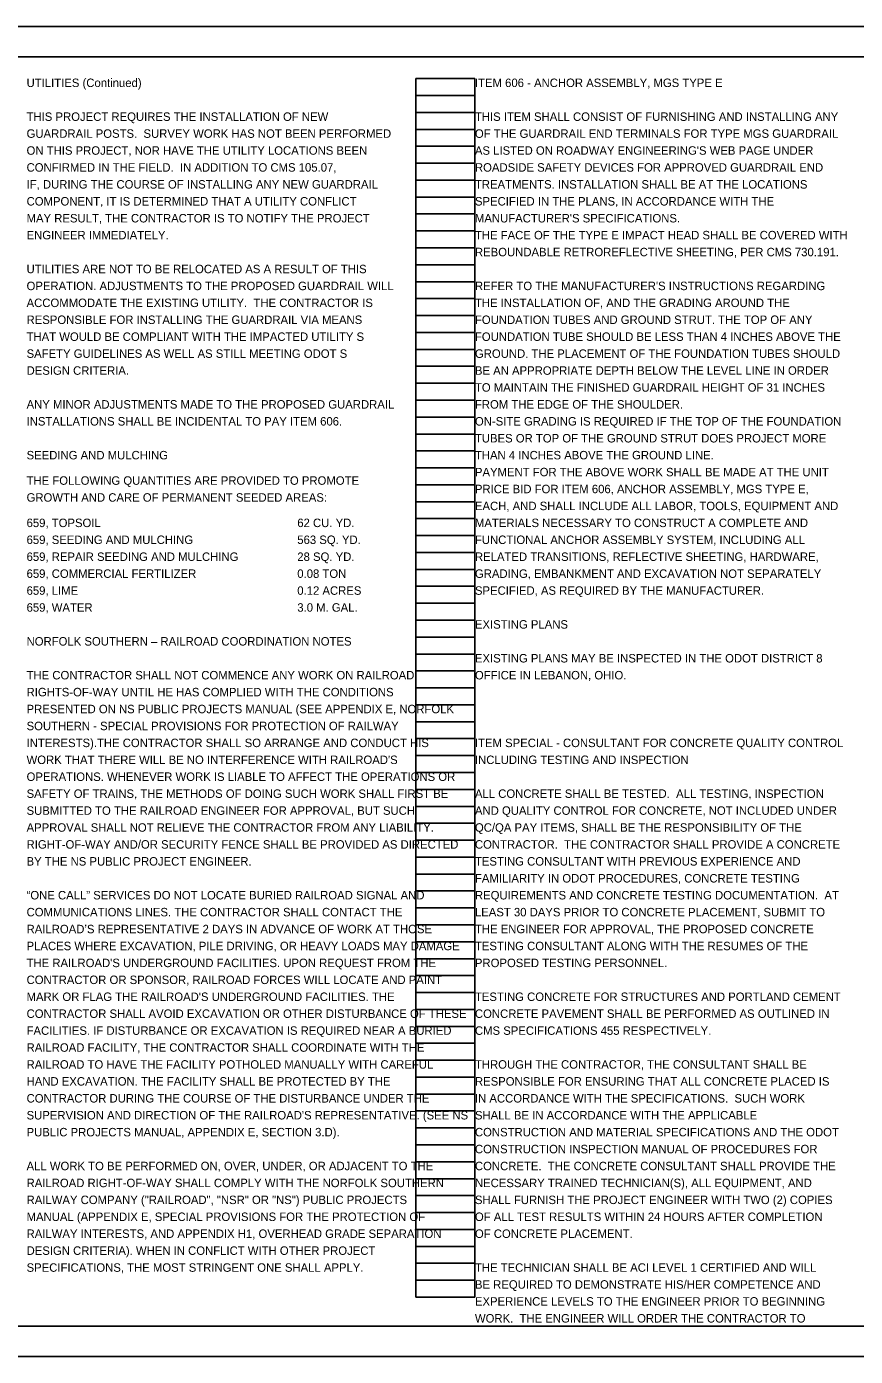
# Model space of a CAD drawing. Extents: x -15.3 to 74.8, y -11.5 to 47.6.
# Drawn here: x 9.82 to 23.54, y 0 to 22 of the extents above; entities that cross this region are included whole.
import ezdxf

# ---------------------------------------------------------------- set-up
doc = ezdxf.new("R2010")
doc.units = 0
for name, color, linetype in [('Default', 7, 'Continuous'), ('SH_Border', 7, 'Continuous'), ('SH_Cut_Line', 7, 'Continuous'), ('SH_Data', 7, 'Continuous'), ('SH_Text', 7, 'Continuous')]:
    doc.layers.add(name, color=color, linetype=linetype)

msp = doc.modelspace()

# ---------------------------------------------------------------- linework, layer by layer
at = {"layer": 'SH_Border'}
msp.add_lwpolyline([(1.5, 21.5), (33.5, 21.5), (33.5, 0.5), (1.5, 0.5)], close=True, dxfattribs=at)
at = {"layer": 'SH_Cut_Line'}
msp.add_lwpolyline([(0, 0), (34, 0), (34, 22), (0, 22)], close=True, dxfattribs=at)
at = {"layer": 'SH_Data'}
for p, q in [((16.26, 0.98), (16.26, 21.14)), ((16.26, 21.14), (17.24, 21.14)), ((17.24, 0.98), (17.24, 21.14)), ((16.26, 20.86), (17.24, 20.86)), ((16.26, 20.58), (17.24, 20.58)), ((16.26, 20.3), (17.24, 20.3)), ((16.26, 20.02), (17.24, 20.02)), ((16.26, 19.74), (17.24, 19.74)), ((16.26, 19.46), (17.24, 19.46)), ((16.26, 19.18), (17.24, 19.18)), ((16.26, 18.9), (17.24, 18.9)), ((16.26, 18.62), (17.24, 18.62)), ((16.26, 18.34), (17.24, 18.34)), ((16.26, 18.06), (17.24, 18.06)), ((16.26, 17.78), (17.24, 17.78)), ((16.26, 17.5), (17.24, 17.5)), ((16.26, 17.22), (17.24, 17.22)), ((16.26, 16.94), (17.24, 16.94)), ((16.26, 16.66), (17.24, 16.66)), ((16.26, 16.38), (17.24, 16.38)), ((16.26, 16.1), (17.24, 16.1)), ((16.26, 15.82), (17.24, 15.82)), ((16.26, 15.54), (17.24, 15.54)), ((16.26, 15.26), (17.24, 15.26)), ((16.26, 14.98), (17.24, 14.98)), ((16.26, 14.7), (17.24, 14.7)), ((16.26, 14.42), (17.24, 14.42)), ((16.26, 14.14), (17.24, 14.14)), ((16.26, 13.86), (17.24, 13.86)), ((16.26, 13.58), (17.24, 13.58)), ((16.26, 13.3), (17.24, 13.3)), ((16.26, 13.02), (17.24, 13.02)), ((16.26, 12.74), (17.24, 12.74)), ((16.26, 12.46), (17.24, 12.46)), ((16.26, 12.18), (17.24, 12.18)), ((16.26, 11.9), (17.24, 11.9)), ((16.26, 11.62), (17.24, 11.62)), ((16.26, 11.34), (17.24, 11.34)), ((16.26, 11.06), (17.24, 11.06)), ((16.26, 10.78), (17.24, 10.78)), ((16.26, 10.5), (17.24, 10.5)), ((16.26, 10.22), (17.24, 10.22)), ((16.26, 9.94), (17.24, 9.94)), ((16.26, 9.66), (17.24, 9.66)), ((16.26, 9.38), (17.24, 9.38)), ((16.26, 9.1), (17.24, 9.1)), ((16.26, 8.82), (17.24, 8.82)), ((16.26, 8.54), (17.24, 8.54)), ((16.26, 8.26), (17.24, 8.26)), ((16.26, 7.98), (17.24, 7.98)), ((16.26, 7.7), (17.24, 7.7)), ((16.26, 7.42), (17.24, 7.42)), ((16.26, 7.14), (17.24, 7.14)), ((16.26, 6.86), (17.24, 6.86)), ((16.26, 6.58), (17.24, 6.58)), ((16.26, 6.3), (17.24, 6.3)), ((16.26, 6.02), (17.24, 6.02)), ((16.26, 5.74), (17.24, 5.74)), ((16.26, 5.46), (17.24, 5.46)), ((16.26, 5.18), (17.24, 5.18)), ((16.26, 4.9), (17.24, 4.9)), ((16.26, 4.62), (17.24, 4.62)), ((16.26, 4.34), (17.24, 4.34)), ((16.26, 4.06), (17.24, 4.06)), ((16.26, 3.78), (17.24, 3.78)), ((16.26, 3.5), (17.24, 3.5)), ((16.26, 3.22), (17.24, 3.22)), ((16.26, 2.94), (17.24, 2.94)), ((16.26, 2.66), (17.24, 2.66)), ((16.26, 2.38), (17.24, 2.38)), ((16.26, 2.1), (17.24, 2.1)), ((16.26, 1.82), (17.24, 1.82)), ((16.26, 1.54), (17.24, 1.54)), ((16.26, 1.26), (17.24, 1.26)), ((16.26, 0.98), (17.24, 0.98))]:
    msp.add_line(p, q, dxfattribs=at)

# ---------------------------------------------------------------- texts
at = {"layer": 'Default'}
for s, p in [('UTILITIES (Continued)', (9.82, 21)), ('THIS PROJECT REQUIRES THE INSTALLATION OF NEW ', (9.82, 20.44)), ('GUARDRAIL POSTS.  SURVEY WORK HAS NOT BEEN PERFORMED ', (9.82, 20.16)), ('ON THIS PROJECT, NOR HAVE THE UTILITY LOCATIONS BEEN ', (9.82, 19.88)), ('CONFIRMED IN THE FIELD.  IN ADDITION TO CMS 105.07, ', (9.82, 19.6)), ('IF, DURING THE COURSE OF INSTALLING ANY NEW GUARDRAIL ', (9.82, 19.32)), ('COMPONENT, IT IS DETERMINED THAT A UTILITY CONFLICT ', (9.82, 19.04)), ('MAY RESULT, THE CONTRACTOR IS TO NOTIFY THE PROJECT ', (9.82, 18.76)), ('ENGINEER IMMEDIATELY.  ', (9.82, 18.48)), ('UTILITIES ARE NOT TO BE RELOCATED AS A RESULT OF THIS ', (9.82, 17.92)), ('OPERATION. ADJUSTMENTS TO THE PROPOSED GUARDRAIL WILL ', (9.82, 17.64)), ('ACCOMMODATE THE EXISTING UTILITY.  THE CONTRACTOR IS ', (9.82, 17.36)), ('RESPONSIBLE FOR INSTALLING THE GUARDRAIL VIA MEANS ', (9.82, 17.08)), ('THAT WOULD BE COMPLIANT WITH THE IMPACTED UTILITY S ', (9.82, 16.8)), ('SAFETY GUIDELINES AS WELL AS STILL MEETING ODOT S ', (9.82, 16.52)), ('DESIGN CRITERIA.  ', (9.82, 16.24)), ('ANY MINOR ADJUSTMENTS MADE TO THE PROPOSED GUARDRAIL ', (9.82, 15.68)), ('INSTALLATIONS SHALL BE INCIDENTAL TO PAY ITEM 606.', (9.82, 15.4)), ('ITEM SPECIAL - CONSULTANT FOR CONCRETE QUALITY CONTROL ', (17.24, 10.08)), ('INCLUDING TESTING AND INSPECTION', (17.24, 9.8)), ('ALL CONCRETE SHALL BE TESTED.  ALL TESTING, INSPECTION ', (17.24, 9.24)), ('AND QUALITY CONTROL FOR CONCRETE, NOT INCLUDED UNDER ', (17.24, 8.96)), ('QC/QA PAY ITEMS, SHALL BE THE RESPONSIBILITY OF THE ', (17.24, 8.68)), ('CONTRACTOR.  THE CONTRACTOR SHALL PROVIDE A CONCRETE ', (17.24, 8.4)), ('TESTING CONSULTANT WITH PREVIOUS EXPERIENCE AND ', (17.24, 8.12)), ('FAMILIARITY IN ODOT PROCEDURES, CONCRETE TESTING ', (17.24, 7.84)), ('REQUIREMENTS AND CONCRETE TESTING DOCUMENTATION.  AT ', (17.24, 7.56)), ('LEAST 30 DAYS PRIOR TO CONCRETE PLACEMENT, SUBMIT TO ', (17.24, 7.28)), ('THE ENGINEER FOR APPROVAL, THE PROPOSED CONCRETE ', (17.24, 7)), ('TESTING CONSULTANT ALONG WITH THE RESUMES OF THE ', (17.24, 6.72)), ('PROPOSED TESTING PERSONNEL.  ', (17.24, 6.44)), ('TESTING CONCRETE FOR STRUCTURES AND PORTLAND CEMENT ', (17.24, 5.88)), ('CONCRETE PAVEMENT SHALL BE PERFORMED AS OUTLINED IN ', (17.24, 5.6)), ('CMS SPECIFICATIONS 455 RESPECTIVELY.', (17.24, 5.32)), ('THROUGH THE CONTRACTOR, THE CONSULTANT SHALL BE ', (17.24, 4.76)), ('RESPONSIBLE FOR ENSURING THAT ALL CONCRETE PLACED IS ', (17.24, 4.48)), ('IN ACCORDANCE WITH THE SPECIFICATIONS.  SUCH WORK ', (17.24, 4.2)), ('SHALL BE IN ACCORDANCE WITH THE APPLICABLE ', (17.24, 3.92)), ('CONSTRUCTION AND MATERIAL SPECIFICATIONS AND THE ODOT ', (17.24, 3.64)), ('CONSTRUCTION INSPECTION MANUAL OF PROCEDURES FOR ', (17.24, 3.36)), ('CONCRETE.  THE CONCRETE CONSULTANT SHALL PROVIDE THE ', (17.24, 3.08)), ('NECESSARY TRAINED TECHNICIAN(S), ALL EQUIPMENT, AND ', (17.24, 2.8)), ('SHALL FURNISH THE PROJECT ENGINEER WITH TWO (2) COPIES ', (17.24, 2.52)), ('OF ALL TEST RESULTS WITHIN 24 HOURS AFTER COMPLETION ', (17.24, 2.24)), ('OF CONCRETE PLACEMENT.', (17.24, 1.96)), ('THE TECHNICIAN SHALL BE ACI LEVEL 1 CERTIFIED AND WILL ', (17.24, 1.4)), ('BE REQUIRED TO DEMONSTRATE HIS/HER COMPETENCE AND ', (17.24, 1.12)), ('EXPERIENCE LEVELS TO THE ENGINEER PRIOR TO BEGINNING ', (17.24, 0.84)), ('WORK.  THE ENGINEER WILL ORDER THE CONTRACTOR TO', (17.24, 0.56))]:
    msp.add_text(s, height=0.14, dxfattribs=at).set_placement(p)
at = {"layer": 'SH_Text'}
for s, p in [('ITEM 606 - ANCHOR ASSEMBLY, MGS TYPE E', (17.24, 21)), ('THIS ITEM SHALL CONSIST OF FURNISHING AND INSTALLING ANY', (17.24, 20.44)), ('OF THE GUARDRAIL END TERMINALS FOR TYPE MGS GUARDRAIL', (17.24, 20.16)), ("AS LISTED ON ROADWAY ENGINEERING'S WEB PAGE UNDER", (17.24, 19.88)), ('ROADSIDE SAFETY DEVICES FOR APPROVED GUARDRAIL END', (17.24, 19.6)), ('TREATMENTS. INSTALLATION SHALL BE AT THE LOCATIONS', (17.24, 19.32)), ('SPECIFIED IN THE PLANS, IN ACCORDANCE WITH THE', (17.24, 19.04)), ("MANUFACTURER'S SPECIFICATIONS.", (17.24, 18.76)), ('THE FACE OF THE TYPE E IMPACT HEAD SHALL BE COVERED WITH ', (17.24, 18.48)), ('REBOUNDABLE RETROREFLECTIVE SHEETING, PER CMS 730.191.', (17.24, 18.2)), ("REFER TO THE MANUFACTURER'S INSTRUCTIONS REGARDING", (17.24, 17.64)), ('THE INSTALLATION OF, AND THE GRADING AROUND THE', (17.24, 17.36)), ('FOUNDATION TUBES AND GROUND STRUT. THE TOP OF ANY', (17.24, 17.08)), ('FOUNDATION TUBE SHOULD BE LESS THAN 4 INCHES ABOVE THE', (17.24, 16.8)), ('GROUND. THE PLACEMENT OF THE FOUNDATION TUBES SHOULD', (17.24, 16.52)), ('BE AN APPROPRIATE DEPTH BELOW THE LEVEL LINE IN ORDER', (17.24, 16.24)), ('TO MAINTAIN THE FINISHED GUARDRAIL HEIGHT OF 31 INCHES', (17.24, 15.96)), ('FROM THE EDGE OF THE SHOULDER.', (17.24, 15.68)), ('ON-SITE GRADING IS REQUIRED IF THE TOP OF THE FOUNDATION', (17.24, 15.4)), ('TUBES OR TOP OF THE GROUND STRUT DOES PROJECT MORE', (17.24, 15.12)), ('SEEDING AND MULCHING', (9.82, 14.84)), ('THAN 4 INCHES ABOVE THE GROUND LINE.', (17.24, 14.84)), ('THE FOLLOWING QUANTITIES ARE PROVIDED TO PROMOTE', (9.82, 14.42)), ('PAYMENT FOR THE ABOVE WORK SHALL BE MADE AT THE UNIT', (17.24, 14.56)), ('PRICE BID FOR ITEM 606, ANCHOR ASSEMBLY, MGS TYPE E,', (17.24, 14.28)), ('GROWTH AND CARE OF PERMANENT SEEDED AREAS:', (9.82, 14.14)), ('EACH, AND SHALL INCLUDE ALL LABOR, TOOLS, EQUIPMENT AND', (17.24, 14)), ('659, TOPSOIL                      ', (9.82, 13.72)), ('62 CU. YD.', (14.3, 13.72)), ('MATERIALS NECESSARY TO CONSTRUCT A COMPLETE AND', (17.24, 13.72)), ('659, SEEDING AND MULCHING         ', (9.82, 13.44)), ('563 SQ. YD.', (14.3, 13.44)), ('FUNCTIONAL ANCHOR ASSEMBLY SYSTEM, INCLUDING ALL', (17.24, 13.44)), ('659, REPAIR SEEDING AND MULCHING   ', (9.82, 13.16)), ('28 SQ. YD.', (14.3, 13.16)), ('RELATED TRANSITIONS, REFLECTIVE SHEETING, HARDWARE,', (17.24, 13.16)), ('659, COMMERCIAL FERTILIZER         ', (9.82, 12.88)), ('0.08 TON', (14.3, 12.88)), ('GRADING, EMBANKMENT AND EXCAVATION NOT SEPARATELY', (17.24, 12.88)), ('659, LIME                          ', (9.82, 12.6)), ('0.12 ACRES', (14.3, 12.6)), ('SPECIFIED, AS REQUIRED BY THE MANUFACTURER.', (17.24, 12.6)), ('659, WATER                        ', (9.82, 12.32)), ('3.0 M. GAL.', (14.3, 12.32)), ('EXISTING PLANS', (17.24, 12.04)), ('NORFOLK SOUTHERN – RAILROAD COORDINATION NOTES', (9.82, 11.76)), ('EXISTING PLANS MAY BE INSPECTED IN THE ODOT DISTRICT 8', (17.24, 11.48)), ('THE CONTRACTOR SHALL NOT COMMENCE ANY WORK ON RAILROAD ', (9.82, 11.2)), ('OFFICE IN LEBANON, OHIO.', (17.24, 11.2)), ('RIGHTS-OF-WAY UNTIL HE HAS COMPLIED WITH THE CONDITIONS ', (9.82, 10.92)), ('PRESENTED ON NS PUBLIC PROJECTS MANUAL (SEE APPENDIX E, NORFOLK ', (9.82, 10.64)), ('SOUTHERN - SPECIAL PROVISIONS FOR PROTECTION OF RAILWAY ', (9.82, 10.36)), ('INTERESTS).THE CONTRACTOR SHALL SO ARRANGE AND CONDUCT HIS ', (9.82, 10.08)), ("WORK THAT THERE WILL BE NO INTERFERENCE WITH RAILROAD'S ", (9.82, 9.8)), ('OPERATIONS. WHENEVER WORK IS LIABLE TO AFFECT THE OPERATIONS OR ', (9.82, 9.52)), ('SAFETY OF TRAINS, THE METHODS OF DOING SUCH WORK SHALL FIRST BE ', (9.82, 9.24)), ('SUBMITTED TO THE RAILROAD ENGINEER FOR APPROVAL, BUT SUCH ', (9.82, 8.96)), ('APPROVAL SHALL NOT RELIEVE THE CONTRACTOR FROM ANY LIABILITY. ', (9.82, 8.68)), ('RIGHT-OF-WAY AND/OR SECURITY FENCE SHALL BE PROVIDED AS DIRECTED ', (9.82, 8.4)), ('BY THE NS PUBLIC PROJECT ENGINEER.', (9.82, 8.12)), ('“ONE CALL” SERVICES DO NOT LOCATE BURIED RAILROAD SIGNAL AND ', (9.82, 7.56)), ('COMMUNICATIONS LINES. THE CONTRACTOR SHALL CONTACT THE ', (9.82, 7.28)), ('RAILROAD’S REPRESENTATIVE 2 DAYS IN ADVANCE OF WORK AT THOSE ', (9.82, 7)), ('PLACES WHERE EXCAVATION, PILE DRIVING, OR HEAVY LOADS MAY DAMAGE ', (9.82, 6.72)), ("THE RAILROAD'S UNDERGROUND FACILITIES. UPON REQUEST FROM THE ", (9.82, 6.44)), ('CONTRACTOR OR SPONSOR, RAILROAD FORCES WILL LOCATE AND PAINT ', (9.82, 6.16)), ("MARK OR FLAG THE RAILROAD'S UNDERGROUND FACILITIES. THE ", (9.82, 5.88)), ('CONTRACTOR SHALL AVOID EXCAVATION OR OTHER DISTURBANCE OF THESE ', (9.82, 5.6)), ('FACILITIES. IF DISTURBANCE OR EXCAVATION IS REQUIRED NEAR A BURIED ', (9.82, 5.32)), ('RAILROAD FACILITY, THE CONTRACTOR SHALL COORDINATE WITH THE ', (9.82, 5.04)), ('RAILROAD TO HAVE THE FACILITY POTHOLED MANUALLY WITH CAREFUL ', (9.82, 4.76)), ('HAND EXCAVATION. THE FACILITY SHALL BE PROTECTED BY THE ', (9.82, 4.48)), ('CONTRACTOR DURING THE COURSE OF THE DISTURBANCE UNDER THE ', (9.82, 4.2)), ("SUPERVISION AND DIRECTION OF THE RAILROAD'S REPRESENTATIVE. (SEE NS ", (9.82, 3.92)), ('PUBLIC PROJECTS MANUAL, APPENDIX E, SECTION 3.D).', (9.82, 3.64)), ('ALL WORK TO BE PERFORMED ON, OVER, UNDER, OR ADJACENT TO THE ', (9.82, 3.08)), ('RAILROAD RIGHT-OF-WAY SHALL COMPLY WITH THE NORFOLK SOUTHERN ', (9.82, 2.8)), ('RAILWAY COMPANY ("RAILROAD", "NSR" OR "NS") PUBLIC PROJECTS ', (9.82, 2.52)), ('MANUAL (APPENDIX E, SPECIAL PROVISIONS FOR THE PROTECTION OF ', (9.82, 2.24)), ('RAILWAY INTERESTS, AND APPENDIX H1, OVERHEAD GRADE SEPARATION ', (9.82, 1.96)), ('DESIGN CRITERIA). WHEN IN CONFLICT WITH OTHER PROJECT ', (9.82, 1.68)), ('SPECIFICATIONS, THE MOST STRINGENT ONE SHALL APPLY.', (9.82, 1.4))]:
    msp.add_text(s, height=0.14, dxfattribs=at).set_placement(p)

doc.saveas('drawing.dxf')
